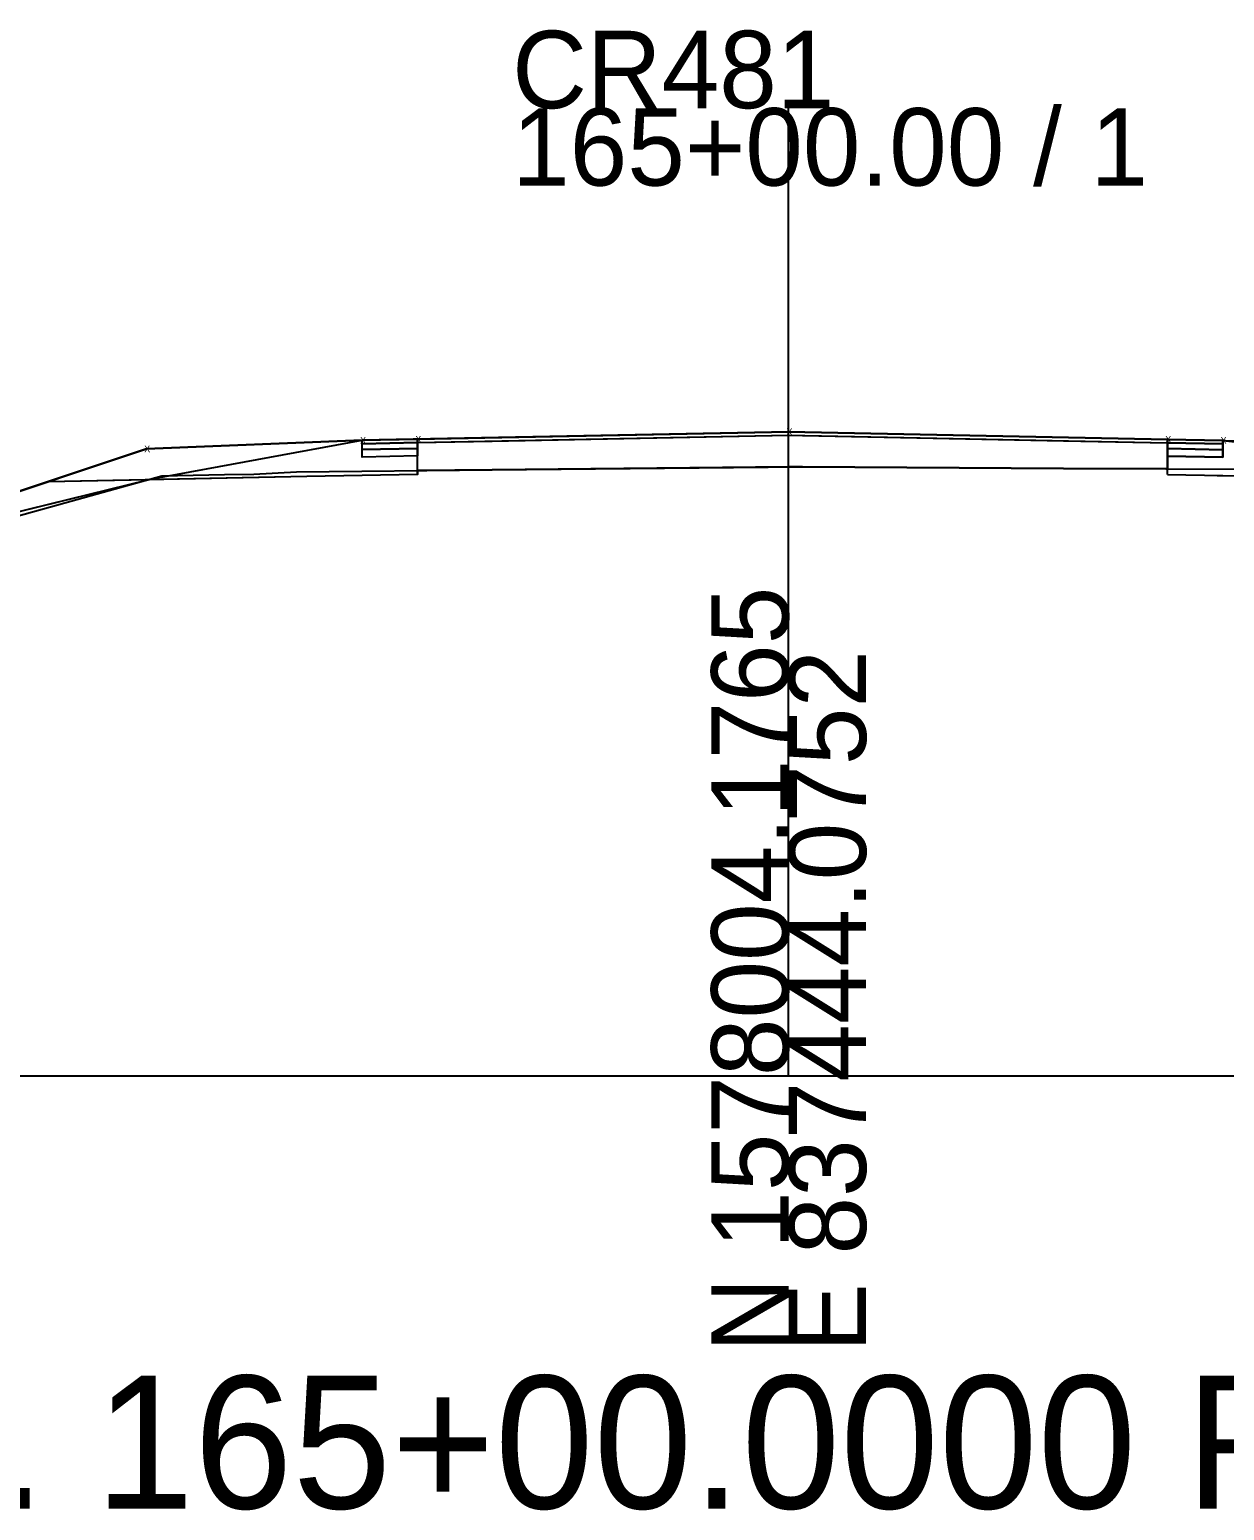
# Model space of a CAD drawing. Extents: x -26 to 303, y -16 to 6048.
# Drawn here: x 122.5 to 165.8, y 3484.3 to 3537.8 of the extents above; entities that cross this region are included whole.
import ezdxf

# ---------------------------------------------------------------- set-up
doc = ezdxf.new("R2010")
doc.units = 0
for name, color, linetype in [('ASPHALT_19MM1', 7, 'Continuous'), ('ASPHALT_9_5MM1', 7, 'Continuous'), ('CONST_LV3', 7, 'Continuous'), ('Draft_XS_Text', 7, 'Continuous'), ('DTM_P_FINISHED_GRADE2', 7, 'Continuous'), ('DTM_X_GROUND', 7, 'Continuous'), ('TRANS_PAVED_SHOULDERS', 7, 'Continuous'), ('X_PROFILES_1', 7, 'Continuous'), ('XS_CELL', 7, 'Continuous'), ('XS_M_SHAPES_EARTHWORK', 7, 'Continuous'), ('XS_P_ASPHALT', 7, 'Continuous'), ('XS_P_GROUND', 7, 'Continuous'), ('XS_P_NULL_POINT', 7, 'Continuous'), ('XS_P_SHOULDER', 7, 'Continuous'), ('XS_P_SUBGRADE_GRANULAR', 7, 'Continuous'), ('XS_P_SUBGRADE_LEVELING', 7, 'Continuous'), ('XS_P_SUBGRADE_MILLING', 7, 'Continuous')]:
    doc.layers.add(name, color=color, linetype=linetype)

msp = doc.modelspace()

# ---------------------------------------------------------------- linework, layer by layer
at = {"layer": 'ASPHALT_19MM1'}
for points in [[(136.577, 3522.694), (136.577, 3522.423), (134.577, 3522.383), (134.577, 3522.654), (136.577, 3522.694)], [(163.707, 3522.688), (163.707, 3522.417), (165.707, 3522.377), (165.707, 3522.648), (163.707, 3522.688)]]:
    msp.add_lwpolyline(points, dxfattribs=at)
at = {"layer": 'ASPHALT_9_5MM1'}
for points in [[(136.577, 3523.027), (136.577, 3522.902), (134.577, 3522.862), (134.577, 3522.987), (136.577, 3523.027)], [(163.707, 3523.022), (163.707, 3522.897), (165.707, 3522.857), (165.707, 3522.982), (163.707, 3523.022)]]:
    msp.add_lwpolyline(points, dxfattribs=at)
at = {"layer": 'CONST_LV3'}
for points in [[(150, 3523.296), (134.577, 3522.987)], [(150, 3523.296), (165.506, 3522.986)]]:
    msp.add_lwpolyline(points, dxfattribs=at)
at = {"layer": 'DTM_P_FINISHED_GRADE2'}
msp.add_lwpolyline([(113.908, 3518.388), (113.943, 3518.4), (126.768, 3522.675), (126.77, 3522.675), (134.577, 3522.987), (136.577, 3523.027), (150, 3523.296), (163.705, 3523.022), (163.707, 3523.022), (165.706, 3522.982), (165.707, 3522.982)], dxfattribs=at)
at = {"layer": 'DTM_X_GROUND'}
for points in [[(96.02, 3516.501), (102.4, 3517.392), (106.129, 3517.912), (107.037, 3517.989), (108.507, 3518.114), (113.908, 3518.388), (113.908, 3518.388), (113.942, 3518.396), (113.959, 3518.4), (126.975, 3521.598), (134.577, 3522.987), (134.577, 3522.987), (134.577, 3522.987), (136.577, 3523.027), (136.578, 3523.027), (150, 3523.296), (163.705, 3523.022), (163.707, 3523.022), (165.706, 3522.982), (165.707, 3522.982), (165.707, 3522.982), (170.73, 3522.431)], [(96.02, 3516.501), (102.4, 3517.392), (107.037, 3518.039), (115.756, 3518.481), (127.327, 3521.698), (129.588, 3521.745), (130.655, 3521.767), (132.204, 3521.843), (139.271, 3521.919), (150.5, 3522.03), (159.946, 3521.966), (171.035, 3521.93), (173.489, 3521.967), (174.598, 3521.727), (182.289, 3521.341), (183.914, 3521.26), (186.242, 3520.917), (195.662, 3520.649), (196.283, 3520.634), (205.45, 3520.374)]]:
    msp.add_lwpolyline(points, dxfattribs=at)
at = {"layer": 'TRANS_PAVED_SHOULDERS'}
for points in [[(136.577, 3522.902), (136.577, 3522.694), (134.577, 3522.654), (134.577, 3522.862), (136.577, 3522.902)], [(163.707, 3522.897), (163.707, 3522.688), (165.707, 3522.648), (165.707, 3522.857), (163.707, 3522.897)]]:
    msp.add_lwpolyline(points, dxfattribs=at)
at = {"layer": 'XS_CELL'}
for p, q in [((150, 3500), (150, 3535)), ((0, 3500), (150, 3500)), ((150, 3500), (300, 3500))]:
    msp.add_line(p, q, dxfattribs=at)
at = {"layer": 'XS_M_SHAPES_EARTHWORK'}
for points in [[(126.824, 3521.561), (126.975, 3521.598), (134.577, 3522.987), (136.577, 3523.027), (136.578, 3523.027), (150, 3523.296), (163.705, 3523.022), (163.707, 3523.022), (165.706, 3522.982), (165.764, 3522.975), (165.707, 3522.978), (165.707, 3522.857), (165.707, 3522.648), (165.707, 3522.377), (163.707, 3522.417), (163.707, 3521.953), (159.945, 3521.966), (150.5, 3522.03), (150, 3522.025), (139.272, 3521.919), (139.271, 3521.919), (136.577, 3521.89), (136.577, 3521.756), (134.577, 3521.716), (132.577, 3521.676)], [(113.908, 3518.388), (113.942, 3518.396), (113.959, 3518.4), (126.824, 3521.561), (123.212, 3521.489)]]:
    msp.add_lwpolyline(points, close=True, dxfattribs=at)
at = {"layer": 'XS_P_ASPHALT'}
msp.add_lwpolyline([(136.577, 3523.027), (136.577, 3522.902), (136.578, 3522.902), (150, 3523.171), (163.705, 3522.897), (163.707, 3522.897), (163.707, 3523.022), (163.707, 3523.022), (163.705, 3523.022), (150, 3523.296), (136.578, 3523.027), (136.577, 3523.027), (136.577, 3523.027)], dxfattribs=at)
at = {"layer": 'XS_P_GROUND'}
for points in [[(126.77, 3522.675), (102.263, 3514.506)], [(113.908, 3518.388), (126.768, 3522.675), (126.77, 3522.675)]]:
    msp.add_lwpolyline(points, dxfattribs=at)
at = {"layer": 'XS_P_SHOULDER'}
for points in [[(134.577, 3522.987), (126.77, 3522.675)], [(134.577, 3522.987), (126.77, 3522.675)], [(165.506, 3522.986), (173.29, 3522.674)]]:
    msp.add_lwpolyline(points, dxfattribs=at)
at = {"layer": 'XS_P_SUBGRADE_GRANULAR'}
for points in [[(136.577, 3521.756), (136.577, 3523.027)], [(163.707, 3521.751), (163.707, 3523.022)], [(134.577, 3521.716), (132.577, 3521.676), (123.212, 3521.489)], [(134.577, 3521.716), (132.577, 3521.676), (123.212, 3521.489)], [(134.577, 3521.716), (132.577, 3521.676), (123.212, 3521.489)], [(136.577, 3521.756), (134.577, 3521.716)], [(163.707, 3521.751), (165.707, 3521.711)], [(165.506, 3521.715), (167.506, 3521.675), (176.849, 3521.488)], [(165.506, 3521.715), (167.506, 3521.675), (176.849, 3521.488)]]:
    msp.add_lwpolyline(points, dxfattribs=at)
at = {"layer": 'XS_P_SUBGRADE_LEVELING'}
msp.add_lwpolyline([(163.706, 3522.897), (163.707, 3522.897), (163.707, 3522.897), (163.707, 3521.953), (163.706, 3521.953), (159.946, 3521.966), (159.945, 3521.966), (150.5, 3522.03), (150.5, 3522.03), (150, 3522.025), (139.272, 3521.919), (139.271, 3521.919), (136.577, 3521.89), (136.577, 3521.89), (136.577, 3522.902), (136.577, 3522.902), (136.577, 3522.902), (139.271, 3522.956), (139.272, 3522.956), (150, 3523.171), (150.5, 3523.161), (150.5, 3523.161), (159.945, 3522.972), (159.946, 3522.972), (163.706, 3522.897)], dxfattribs=at)
at = {"layer": 'XS_P_SUBGRADE_MILLING'}
msp.add_lwpolyline([(136.577, 3521.89), (136.577, 3521.89), (139.271, 3521.919), (139.272, 3521.919), (150, 3522.025), (150.5, 3522.03), (150.5, 3522.03), (159.945, 3521.966), (159.946, 3521.966), (163.706, 3521.953), (163.707, 3521.953)], dxfattribs=at)
msp.add_lwpolyline([(136.577, 3521.89), (136.577, 3521.89), (139.271, 3521.919), (139.272, 3521.919), (150, 3522.025), (150.5, 3522.03), (150.5, 3522.03), (159.945, 3521.966), (159.946, 3521.966), (163.706, 3521.953), (163.707, 3521.953)], dxfattribs=at)

# ---------------------------------------------------------------- texts
at = {"layer": 'Draft_XS_Text'}
msp.add_text('Sta. 165+00.0000 R1', height=4.8, dxfattribs=at).set_placement((111.716, 3484.35))
at = {"layer": 'X_PROFILES_1'}
msp.add_text('X', height=0.24, dxfattribs=at).set_placement((126.691, 3522.555))
at = {"layer": 'XS_CELL'}
for s, p in [('CR481', (140, 3535)), ('165+00.00 / 1', (140, 3532.2))]:
    msp.add_text(s, height=2.8, dxfattribs=at).set_placement(p)
for s, p in [('N 1578004.1765', (150, 3490)), ('E 837444.0752', (152.8, 3490))]:
    msp.add_text(s, height=2.8, rotation=90, dxfattribs=at).set_placement(p)
at = {"layer": 'XS_P_GROUND'}
msp.add_text('X', height=0.24, dxfattribs=at).set_placement((126.691, 3522.555))
at = {"layer": 'XS_P_NULL_POINT'}
for p in [(149.922, 3523.176), (134.498, 3522.867), (136.498, 3522.907), (163.628, 3522.902), (165.628, 3522.862)]:
    msp.add_text('X', height=0.24, dxfattribs=at).set_placement(p)

doc.saveas('drawing.dxf')
